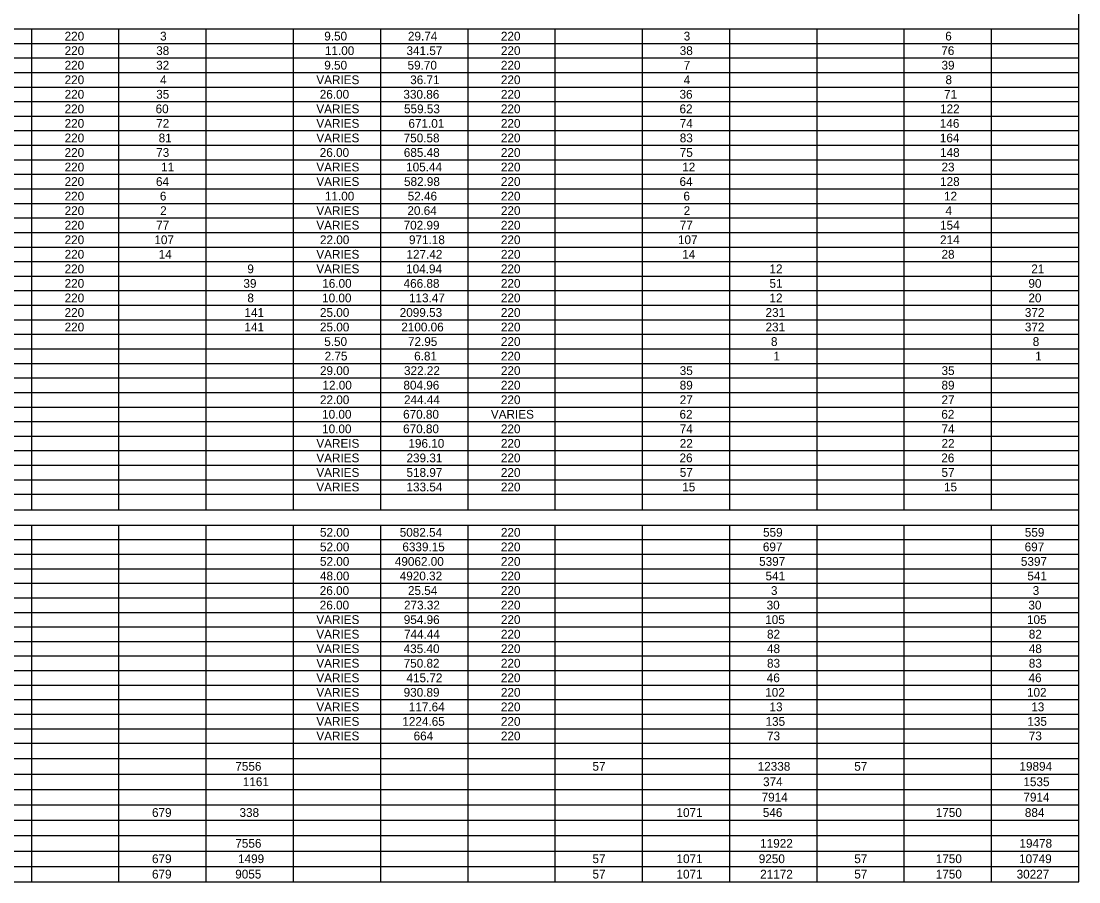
# Model space of a CAD drawing. Extents: x 1226567 to 1228151, y 151309 to 152305.
# Drawn here: x 1227669.3 to 1228150.8, y 151664.6 to 152056.4 of the extents above; entities that cross this region are included whole.
import ezdxf

# ---------------------------------------------------------------- set-up
doc = ezdxf.new("R2010")
doc.units = 0
doc.layers.add('R_Dimension', color=7, linetype='Continuous')

msp = doc.modelspace()

# ---------------------------------------------------------------- linework, layer by layer
at = {"layer": 'R_Dimension'}
for p, q in [((1228150.79, 151664.64), (1228150.79, 152254.68)), ((1226566.84, 152052.93), (1228150.79, 152052.93)), ((1227674.09, 151834.06), (1227674.09, 152052.93)), ((1227713.81, 151834.06), (1227713.81, 152052.93)), ((1227753.54, 151834.06), (1227753.54, 152052.93)), ((1227793.26, 151834.06), (1227793.26, 152052.93)), ((1227832.99, 151834.06), (1227832.99, 152052.93)), ((1227872.71, 151834.06), (1227872.71, 152052.93)), ((1227912.44, 151834.06), (1227912.44, 152052.93)), ((1227952.16, 151834.06), (1227952.16, 152052.93)), ((1227991.89, 151834.06), (1227991.89, 152052.93)), ((1228031.61, 151834.06), (1228031.61, 152052.93)), ((1228071.34, 151834.06), (1228071.34, 152052.93)), ((1228111.06, 151834.06), (1228111.06, 152052.93)), ((1226566.84, 152046.31), (1228150.79, 152046.31)), ((1226566.84, 152039.69), (1228150.79, 152039.69)), ((1226566.84, 152033.07), (1228150.79, 152033.07)), ((1226566.84, 152026.45), (1228150.79, 152026.45)), ((1226566.84, 152019.83), (1228150.79, 152019.83)), ((1226566.84, 152013.21), (1228150.79, 152013.21)), ((1226566.84, 152006.59), (1228150.79, 152006.59)), ((1226566.84, 151999.97), (1228150.79, 151999.97)), ((1226566.84, 151993.35), (1228150.79, 151993.35)), ((1226566.84, 151986.73), (1228150.79, 151986.73)), ((1226566.84, 151980.1), (1228150.79, 151980.1)), ((1226566.84, 151973.48), (1228150.79, 151973.48)), ((1226566.84, 151966.86), (1228150.79, 151966.86)), ((1226566.84, 151960.24), (1228150.79, 151960.24)), ((1226566.84, 151953.62), (1228150.79, 151953.62)), ((1226566.84, 151947), (1228150.79, 151947)), ((1226566.84, 151940.38), (1228150.79, 151940.38)), ((1226566.84, 151933.76), (1228150.79, 151933.76)), ((1226566.84, 151927.14), (1228150.79, 151927.14)), ((1226566.84, 151920.52), (1228150.79, 151920.52)), ((1226566.84, 151913.9), (1228150.79, 151913.9)), ((1226566.84, 151907.27), (1228150.79, 151907.27)), ((1226566.84, 151900.65), (1228150.79, 151900.65)), ((1226566.84, 151894.03), (1228150.79, 151894.03)), ((1226566.84, 151887.41), (1228150.79, 151887.41)), ((1226566.84, 151880.79), (1228150.79, 151880.79)), ((1226566.84, 151874.17), (1228150.79, 151874.17)), ((1226566.84, 151867.55), (1228150.79, 151867.55)), ((1226566.84, 151860.93), (1228150.79, 151860.93)), ((1226566.84, 151854.31), (1228150.79, 151854.31)), ((1226566.84, 151847.69), (1228150.79, 151847.69)), ((1226566.84, 151841.07), (1228150.79, 151841.07)), ((1226566.84, 151834.06), (1228150.79, 151834.06)), ((1226566.84, 151827.05), (1228150.79, 151827.05)), ((1227674.09, 151664.64), (1227674.09, 151827.05)), ((1227713.81, 151664.64), (1227713.81, 151827.05)), ((1227753.54, 151664.64), (1227753.54, 151827.05)), ((1227793.26, 151664.64), (1227793.26, 151827.05)), ((1227832.99, 151664.64), (1227832.99, 151827.05)), ((1227872.71, 151664.64), (1227872.71, 151827.05)), ((1227912.44, 151664.64), (1227912.44, 151827.05)), ((1227952.16, 151664.64), (1227952.16, 151827.05)), ((1227991.89, 151664.64), (1227991.89, 151827.05)), ((1228031.61, 151664.64), (1228031.61, 151827.05)), ((1228071.34, 151664.64), (1228071.34, 151827.05)), ((1228111.06, 151664.64), (1228111.06, 151827.05)), ((1226566.84, 151820.42), (1228150.79, 151820.42)), ((1226566.84, 151813.8), (1228150.79, 151813.8)), ((1226566.84, 151807.18), (1228150.79, 151807.18)), ((1226566.84, 151800.56), (1228150.79, 151800.56)), ((1226566.84, 151793.94), (1228150.79, 151793.94)), ((1226566.84, 151787.32), (1228150.79, 151787.32)), ((1226566.84, 151780.7), (1228150.79, 151780.7)), ((1226566.84, 151774.08), (1228150.79, 151774.08)), ((1226566.84, 151767.46), (1228150.79, 151767.46)), ((1226566.84, 151760.84), (1228150.79, 151760.84)), ((1226566.84, 151754.22), (1228150.79, 151754.22)), ((1226566.84, 151747.6), (1228150.79, 151747.6)), ((1226566.84, 151740.97), (1228150.79, 151740.97)), ((1226566.84, 151734.35), (1228150.79, 151734.35)), ((1226566.84, 151727.73), (1228150.79, 151727.73)), ((1226566.84, 151720.72), (1228150.79, 151720.72)), ((1226566.84, 151713.71), (1228150.79, 151713.71)), ((1226566.84, 151706.7), (1228150.79, 151706.7)), ((1226566.84, 151699.69), (1228150.79, 151699.69)), ((1226566.84, 151692.68), (1228150.79, 151692.68)), ((1226566.84, 151685.67), (1228150.79, 151685.67)), ((1226566.84, 151678.66), (1228150.79, 151678.66)), ((1226566.84, 151671.65), (1228150.79, 151671.65)), ((1226566.84, 151664.64), (1228150.79, 151664.64))]:
    msp.add_line(p, q, dxfattribs=at)

# ---------------------------------------------------------------- texts
for s, height, p in [('220', 3.994, (1227689.06, 152047.63)), ('3', 3.99, (1227732.54, 152047.63)), ('9.50', 3.994, (1227807.26, 152047.63)), ('29.74', 3.994, (1227845.36, 152047.63)), ('220', 3.994, (1227887.68, 152047.63)), ('3', 3.99, (1227970.89, 152047.63)), ('6', 3.99, (1228089.96, 152047.63)), ('220', 3.994, (1227689.06, 152041.01)), ('38', 3.994, (1227730.75, 152041.01)), ('11.00', 3.994, (1227807.57, 152041.01)), ('341.57', 3.994, (1227844.7, 152041.01)), ('220', 3.994, (1227887.68, 152041.01)), ('38', 3.994, (1227969.1, 152041.01)), ('76', 3.994, (1228088.16, 152041.01)), ('220', 3.994, (1227689.06, 152034.38)), ('32', 3.994, (1227730.75, 152034.38)), ('9.50', 3.994, (1227807.26, 152034.38)), ('59.70', 3.994, (1227845.19, 152034.38)), ('220', 3.994, (1227887.68, 152034.38)), ('7', 3.99, (1227970.89, 152034.38)), ('39', 3.994, (1228088.26, 152034.38)), ('220', 3.994, (1227689.06, 152027.76)), ('4', 3.99, (1227732.54, 152027.76)), ('VARIES', 3.994, (1227803.66, 152027.76)), ('36.71', 3.994, (1227846.4, 152027.76)), ('220', 3.994, (1227887.68, 152027.76)), ('4', 3.99, (1227970.89, 152027.76)), ('8', 3.99, (1228090.07, 152027.76)), ('220', 3.994, (1227689.06, 152021.14)), ('35', 3.994, (1227730.75, 152021.14)), ('26.00', 3.994, (1227805.21, 152021.14)), ('330.86', 3.994, (1227843.3, 152021.14)), ('220', 3.994, (1227887.68, 152021.14)), ('36', 3.994, (1227968.99, 152021.14)), ('71', 3.994, (1228089.41, 152021.14)), ('220', 3.994, (1227689.06, 152014.52)), ('60', 3.994, (1227730.48, 152014.52)), ('VARIES', 3.994, (1227803.66, 152014.52)), ('559.53', 3.994, (1227843.57, 152014.52)), ('220', 3.994, (1227887.68, 152014.52)), ('62', 3.994, (1227969, 152014.52)), ('122', 3.994, (1228087.61, 152014.52)), ('220', 3.994, (1227689.06, 152007.9)), ('72', 3.994, (1227730.75, 152007.9)), ('VARIES', 3.994, (1227803.66, 152007.9)), ('671.01', 3.994, (1227845.58, 152007.9)), ('220', 3.994, (1227887.68, 152007.9)), ('74', 3.994, (1227969.1, 152007.9)), ('146', 3.994, (1228087.5, 152007.9)), ('220', 3.994, (1227689.06, 152001.28)), ('81', 3.994, (1227731.88, 152001.28)), ('VARIES', 3.994, (1227803.66, 152001.28)), ('750.58', 3.994, (1227843.41, 152001.28)), ('220', 3.994, (1227887.68, 152001.28)), ('83', 3.994, (1227969.1, 152001.28)), ('164', 3.994, (1228087.52, 152001.28)), ('220', 3.994, (1227689.06, 151994.66)), ('73', 3.994, (1227730.75, 151994.66)), ('26.00', 3.994, (1227805.21, 151994.66)), ('685.48', 3.994, (1227843.48, 151994.66)), ('220', 3.994, (1227887.68, 151994.66)), ('75', 3.994, (1227969.1, 151994.66)), ('148', 3.994, (1228087.61, 151994.66)), ('220', 3.994, (1227689.06, 151988.04)), ('11', 3.994, (1227733.01, 151988.04)), ('VARIES', 3.994, (1227803.66, 151988.04)), ('105.44', 3.994, (1227844.54, 151988.04)), ('220', 3.994, (1227887.68, 151988.04)), ('12', 3.994, (1227970.23, 151988.04)), ('23', 3.994, (1228088.27, 151988.04)), ('220', 3.994, (1227689.06, 151981.42)), ('64', 3.994, (1227730.65, 151981.42)), ('VARIES', 3.994, (1227803.66, 151981.42)), ('582.98', 3.994, (1227843.57, 151981.42)), ('220', 3.994, (1227887.68, 151981.42)), ('64', 3.994, (1227969, 151981.42)), ('128', 3.994, (1228087.61, 151981.42)), ('220', 3.994, (1227689.06, 151974.8)), ('6', 3.99, (1227732.43, 151974.8)), ('11.00', 3.994, (1227807.57, 151974.8)), ('52.46', 3.994, (1227845.25, 151974.8)), ('220', 3.994, (1227887.68, 151974.8)), ('6', 3.99, (1227970.78, 151974.8)), ('12', 3.994, (1228089.41, 151974.8)), ('220', 3.994, (1227689.06, 151968.18)), ('2', 3.99, (1227732.54, 151968.18)), ('VARIES', 3.994, (1227803.66, 151968.18)), ('20.64', 3.994, (1227845.11, 151968.18)), ('220', 3.994, (1227887.68, 151968.18)), ('2', 3.99, (1227970.89, 151968.18)), ('4', 3.99, (1228090.07, 151968.18)), ('220', 3.994, (1227689.06, 151961.55)), ('77', 3.994, (1227730.75, 151961.55)), ('VARIES', 3.994, (1227803.66, 151961.55)), ('702.99', 3.994, (1227843.4, 151961.55)), ('220', 3.994, (1227887.68, 151961.55)), ('77', 3.994, (1227969.1, 151961.55)), ('154', 3.994, (1228087.61, 151961.55)), ('220', 3.994, (1227689.06, 151954.93)), ('107', 3.994, (1227729.93, 151954.93)), ('22.00', 3.994, (1227805.31, 151954.93)), ('971.18', 3.994, (1227845.83, 151954.93)), ('220', 3.994, (1227887.68, 151954.93)), ('107', 3.994, (1227968.28, 151954.93)), ('214', 3.994, (1228087.61, 151954.93)), ('220', 3.994, (1227689.06, 151948.31)), ('14', 3.994, (1227731.88, 151948.31)), ('VARIES', 3.994, (1227803.66, 151948.31)), ('127.42', 3.994, (1227844.7, 151948.31)), ('220', 3.994, (1227887.68, 151948.31)), ('14', 3.994, (1227970.23, 151948.31)), ('28', 3.994, (1228088.27, 151948.31)), ('220', 3.994, (1227689.06, 151941.69)), ('9', 3.99, (1227772.25, 151941.69)), ('VARIES', 3.994, (1227803.66, 151941.69)), ('104.94', 3.994, (1227844.54, 151941.69)), ('220', 3.994, (1227887.68, 151941.69)), ('12', 3.994, (1228009.96, 151941.69)), ('21', 3.994, (1228129.13, 151941.69)), ('220', 3.994, (1227689.06, 151935.07)), ('39', 3.994, (1227770.46, 151935.07)), ('16.00', 3.994, (1227806.35, 151935.07)), ('466.88', 3.994, (1227843.38, 151935.07)), ('220', 3.994, (1227887.68, 151935.07)), ('51', 3.994, (1228009.96, 151935.07)), ('90', 3.994, (1228127.83, 151935.07)), ('220', 3.994, (1227689.06, 151928.45)), ('8', 3.99, (1227772.27, 151928.45)), ('10.00', 3.994, (1227806.28, 151928.45)), ('113.47', 3.994, (1227845.83, 151928.45)), ('220', 3.994, (1227887.68, 151928.45)), ('12', 3.994, (1228009.96, 151928.45)), ('20', 3.994, (1228127.83, 151928.45)), ('220', 3.994, (1227689.06, 151921.83)), ('141', 3.994, (1227770.94, 151921.83)), ('25.00', 3.994, (1227805.31, 151921.83)), ('2099.53', 3.994, (1227841.62, 151921.83)), ('220', 3.994, (1227887.68, 151921.83)), ('231', 3.994, (1228008.16, 151921.83)), ('372', 3.994, (1228126.21, 151921.83)), ('220', 3.994, (1227689.06, 151915.21)), ('141', 3.994, (1227770.94, 151915.21)), ('25.00', 3.994, (1227805.31, 151915.21)), ('2100.06', 3.994, (1227842.33, 151915.21)), ('220', 3.994, (1227887.68, 151915.21)), ('231', 3.994, (1228008.16, 151915.21)), ('372', 3.994, (1228126.21, 151915.21)), ('5.50', 3.994, (1227807.26, 151908.59)), ('72.95', 3.994, (1227845.36, 151908.59)), ('220', 3.994, (1227887.68, 151908.59)), ('8', 3.99, (1228010.62, 151908.59)), ('8', 3.99, (1228129.79, 151908.59)), ('2.75', 3.994, (1227807.43, 151901.97)), ('6.81', 3.994, (1227848.19, 151901.97)), ('220', 3.994, (1227887.68, 151901.97)), ('1', 3.99, (1228011.75, 151901.97)), ('1', 3.99, (1228130.92, 151901.97)), ('29.00', 3.994, (1227805.31, 151895.35)), ('322.22', 3.994, (1227843.57, 151895.35)), ('220', 3.994, (1227887.68, 151895.35)), ('35', 3.994, (1227969.1, 151895.35)), ('35', 3.994, (1228088.27, 151895.35)), ('12.00', 3.994, (1227806.44, 151888.73)), ('804.96', 3.994, (1227843.3, 151888.73)), ('220', 3.994, (1227887.68, 151888.73)), ('89', 3.994, (1227969.08, 151888.73)), ('89', 3.994, (1228088.26, 151888.73)), ('22.00', 3.994, (1227805.31, 151882.1)), ('244.44', 3.994, (1227843.57, 151882.1)), ('220', 3.994, (1227887.68, 151882.1)), ('27', 3.994, (1227969.1, 151882.1)), ('27', 3.994, (1228088.27, 151882.1)), ('10.00', 3.994, (1227806.28, 151875.48)), ('670.80', 3.994, (1227843.15, 151875.48)), ('VARIES', 3.994, (1227883.11, 151875.48)), ('62', 3.994, (1227969, 151875.48)), ('62', 3.994, (1228088.18, 151875.48)), ('10.00', 3.994, (1227806.28, 151868.86)), ('670.80', 3.994, (1227843.15, 151868.86)), ('220', 3.994, (1227887.68, 151868.86)), ('74', 3.994, (1227969.1, 151868.86)), ('74', 3.994, (1228088.27, 151868.86)), ('VAREIS', 3.994, (1227803.66, 151862.24)), ('196.10', 3.994, (1227845.57, 151862.24)), ('220', 3.994, (1227887.68, 151862.24)), ('22', 3.994, (1227969.1, 151862.24)), ('22', 3.994, (1228088.27, 151862.24)), ('VARIES', 3.994, (1227803.66, 151855.62)), ('239.31', 3.994, (1227844.7, 151855.62)), ('220', 3.994, (1227887.68, 151855.62)), ('26', 3.994, (1227968.99, 151855.62)), ('26', 3.994, (1228088.16, 151855.62)), ('VARIES', 3.994, (1227803.66, 151849)), ('518.97', 3.994, (1227844.7, 151849)), ('220', 3.994, (1227887.68, 151849)), ('57', 3.994, (1227969.1, 151849)), ('57', 3.994, (1228088.27, 151849)), ('VARIES', 3.994, (1227803.66, 151842.38)), ('133.54', 3.994, (1227844.7, 151842.38)), ('220', 3.994, (1227887.68, 151842.38)), ('15', 3.994, (1227970.23, 151842.38)), ('15', 3.994, (1228089.41, 151842.38)), ('52.00', 3.994, (1227805.31, 151821.74)), ('5082.54', 3.994, (1227841.62, 151821.74)), ('220', 3.994, (1227887.68, 151821.74)), ('559', 3.994, (1228007.02, 151821.74)), ('559', 3.994, (1228126.19, 151821.74)), ('52.00', 3.994, (1227805.31, 151815.12)), ('6339.15', 3.994, (1227842.82, 151815.12)), ('220', 3.994, (1227887.68, 151815.12)), ('697', 3.994, (1228006.94, 151815.12)), ('697', 3.994, (1228126.11, 151815.12)), ('52.00', 3.994, (1227805.31, 151808.5)), ('49062.00', 3.994, (1227839.4, 151808.5)), ('220', 3.994, (1227887.68, 151808.5)), ('5397', 3.994, (1228005.24, 151808.5)), ('5397', 3.994, (1228124.41, 151808.5)), ('48.00', 3.994, (1227805.31, 151801.88)), ('4920.32', 3.994, (1227841.62, 151801.88)), ('220', 3.994, (1227887.68, 151801.88)), ('541', 3.994, (1228008.16, 151801.88)), ('541', 3.994, (1228127.34, 151801.88)), ('26.00', 3.994, (1227805.21, 151795.25)), ('25.54', 3.994, (1227845.36, 151795.25)), ('220', 3.994, (1227887.68, 151795.25)), ('3', 3.99, (1228010.62, 151795.25)), ('3', 3.99, (1228129.79, 151795.25)), ('26.00', 3.994, (1227805.21, 151788.63)), ('273.32', 3.994, (1227843.57, 151788.63)), ('220', 3.994, (1227887.68, 151788.63)), ('30', 3.994, (1228008.65, 151788.63)), ('30', 3.994, (1228127.83, 151788.63)), ('VARIES', 3.994, (1227803.66, 151782.01)), ('954.96', 3.994, (1227843.46, 151782.01)), ('220', 3.994, (1227887.68, 151782.01)), ('105', 3.994, (1228008.01, 151782.01)), ('105', 3.994, (1228127.18, 151782.01)), ('VARIES', 3.994, (1227803.66, 151775.39)), ('744.44', 3.994, (1227843.57, 151775.39)), ('220', 3.994, (1227887.68, 151775.39)), ('82', 3.994, (1228008.82, 151775.39)), ('82', 3.994, (1228128, 151775.39)), ('VARIES', 3.994, (1227803.66, 151768.77)), ('435.40', 3.994, (1227843.4, 151768.77)), ('220', 3.994, (1227887.68, 151768.77)), ('48', 3.994, (1228008.82, 151768.77)), ('48', 3.994, (1228128, 151768.77)), ('VARIES', 3.994, (1227803.66, 151762.15)), ('750.82', 3.994, (1227843.41, 151762.15)), ('220', 3.994, (1227887.68, 151762.15)), ('83', 3.994, (1228008.82, 151762.15)), ('83', 3.994, (1228128, 151762.15)), ('VARIES', 3.994, (1227803.66, 151755.53)), ('415.72', 3.994, (1227844.7, 151755.53)), ('220', 3.994, (1227887.68, 151755.53)), ('46', 3.994, (1228008.71, 151755.53)), ('46', 3.994, (1228127.89, 151755.53)), ('VARIES', 3.994, (1227803.66, 151748.91)), ('930.89', 3.994, (1227843.4, 151748.91)), ('220', 3.994, (1227887.68, 151748.91)), ('102', 3.994, (1228008.01, 151748.91)), ('102', 3.994, (1228127.18, 151748.91)), ('VARIES', 3.994, (1227803.66, 151742.29)), ('117.64', 3.994, (1227845.74, 151742.29)), ('220', 3.994, (1227887.68, 151742.29)), ('13', 3.994, (1228009.96, 151742.29)), ('13', 3.994, (1228129.13, 151742.29)), ('VARIES', 3.994, (1227803.66, 151735.67)), ('1224.65', 3.994, (1227842.82, 151735.67)), ('220', 3.994, (1227887.68, 151735.67)), ('135', 3.994, (1228008.16, 151735.67)), ('135', 3.994, (1228127.34, 151735.67)), ('VARIES', 3.994, (1227803.66, 151729.05)), ('664', 3.994, (1227847.94, 151729.05)), ('220', 3.994, (1227887.68, 151729.05)), ('73', 3.994, (1228008.82, 151729.05)), ('73', 3.994, (1228128, 151729.05)), ('7556', 3.994, (1227766.78, 151715.22)), ('57', 3.994, (1227929.37, 151715.22)), ('12338', 3.994, (1228004.58, 151715.22)), ('57', 3.994, (1228048.55, 151715.22)), ('19894', 3.994, (1228123.75, 151715.22)), ('1161', 3.994, (1227770.19, 151708.21)), ('374', 3.994, (1228007.03, 151708.21)), ('1535', 3.994, (1228125.55, 151708.21)), ('7914', 3.994, (1228006.37, 151701.2)), ('7914', 3.994, (1228125.55, 151701.2)), ('679', 3.994, (1227728.84, 151694.19)), ('338', 3.994, (1227768.68, 151694.19)), ('1071', 3.994, (1227967.62, 151694.19)), ('546', 3.994, (1228006.92, 151694.19)), ('1750', 3.994, (1228085.65, 151694.19)), ('884', 3.994, (1228126.21, 151694.19)), ('7556', 3.994, (1227766.78, 151680.17)), ('11922', 3.994, (1228005.71, 151680.17)), ('19478', 3.994, (1228123.75, 151680.17)), ('679', 3.994, (1227728.84, 151673.16)), ('1499', 3.994, (1227768, 151673.16)), ('57', 3.994, (1227929.37, 151673.16)), ('1071', 3.994, (1227967.62, 151673.16)), ('9250', 3.994, (1228005.07, 151673.16)), ('57', 3.994, (1228048.55, 151673.16)), ('1750', 3.994, (1228085.65, 151673.16)), ('10749', 3.994, (1228123.58, 151673.16)), ('679', 3.994, (1227728.84, 151666.15)), ('9055', 3.994, (1227766.73, 151666.15)), ('57', 3.994, (1227929.37, 151666.15)), ('1071', 3.994, (1227967.62, 151666.15)), ('21172', 3.994, (1228005.71, 151666.15)), ('57', 3.994, (1228048.55, 151666.15)), ('1750', 3.994, (1228085.65, 151666.15)), ('30227', 3.994, (1228122.46, 151666.15))]:
    msp.add_text(s, height=height, dxfattribs=at).set_placement(p)

doc.saveas('drawing.dxf')
